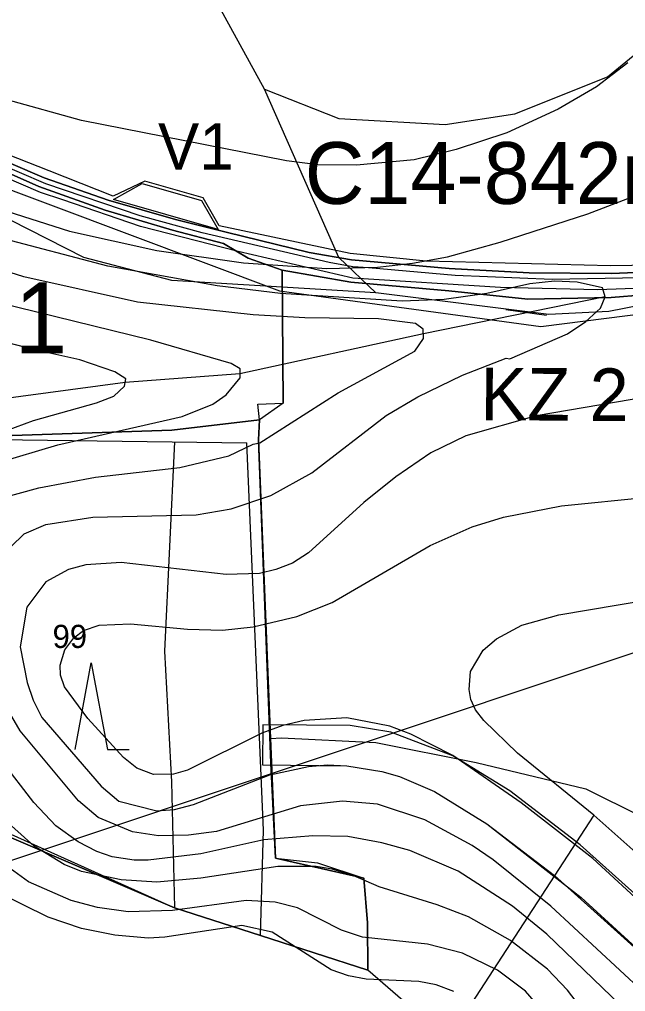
# Model space of a CAD drawing. Extents: x -662500 to -655523, y -1056000 to -1049993.
# Drawn here: x -660890.3 to -660694.1, y -1051979.7 to -1051664.9 of the extents above; entities that cross this region are included whole.
import ezdxf

# ---------------------------------------------------------------- set-up
doc = ezdxf.new("R2010")
doc.units = 0
for name, color, linetype in [('Vrstva 1', 7, 'Continuous'), ('Vrstva 12', 7, 'Continuous'), ('Vrstva 18', 7, 'Continuous'), ('Vrstva 22', 7, 'Continuous'), ('Vrstva 24', 7, 'Continuous'), ('Vrstva 47', 7, 'Continuous'), ('Vrstva 5', 7, 'Continuous'), ('Vrstva 54', 7, 'Continuous'), ('Vrstva 57', 7, 'Continuous'), ('Vrstva 6', 7, 'Continuous'), ('Vrstva 61', 7, 'Continuous'), ('Vrstva 7', 7, 'Continuous')]:
    doc.layers.add(name, color=color, linetype=linetype)

msp = doc.modelspace()

# ---------------------------------------------------------------- linework, layer by layer
at = {"layer": 'Vrstva 1'}
for p, q in [((-660921.87, -1051800.59), (-660816.75, -1051801.98)), ((-660909.2, -1051921.5), (-660840.14, -1051952.57))]:
    msp.add_line(p, q, dxfattribs=at)
msp.add_lwpolyline([(-660840.2, -1051801.67), (-660843.43, -1051869.43), (-660841.15, -1051911.77), (-660840.14, -1051952.57), (-660812.31, -1051961.52), (-660811.36, -1051927.44), (-660816.75, -1051801.98)], dxfattribs=at)
at = {"layer": 'Vrstva 12'}
msp.add_lwpolyline([(-660677.98, -1051748.43), (-660717.94, -1051749.1), (-660749.25, -1051747.86), (-660777.31, -1051745.37), (-660782.46, -1051745.02), (-660790.05, -1051743.6), (-660831.17, -1051734.05), (-660851.28, -1051728.5), (-660881.83, -1051718.2), (-660907.49, -1051707.19), (-660927.4, -1051698.64), (-660936.8, -1051698.75), (-660942.83, -1051699.66), (-660947.81, -1051703.59), (-660954.96, -1051712.4), (-660962.02, -1051729.41), (-660976.83, -1051765.96), (-661003.35, -1051828.87), (-661016.27, -1051860.08), (-661035.12, -1051906.08), (-661051.28, -1051948.02), (-661055.1, -1051959.21), (-661062.47, -1051984.12)], dxfattribs=at)
at = {"layer": 'Vrstva 22'}
msp.add_lwpolyline([(-660535.19, -1052035.73), (-660628.82, -1051995.51), (-660670.4, -1051966.64), (-660708.78, -1051932.15), (-660731.62, -1051914.69), (-660750.01, -1051903.34), (-660770.09, -1051895.71), (-660783.24, -1051893.57), (-660811.55, -1051893.32), (-660811.66, -1051906.32), (-660784.34, -1051906.56), (-660773.01, -1051908.4), (-660767.34, -1051910.1), (-660756, -1051914.92), (-660739, -1051925.41), (-660717.09, -1051942.16), (-660678.48, -1051976.85), (-660636.23, -1052006.19), (-660537.58, -1052047.09)], close=True, dxfattribs=at)
at = {"layer": 'Vrstva 24'}
for points in [[(-660811, -1051687.5), (-660839.5, -1051635.5), (-660864.5, -1051599.5), (-660895, -1051568), (-660922.5, -1051551.5), (-661100, -1051475), (-661134.5, -1051463.5), (-661164.5, -1051456.5), (-661191.5, -1051455), (-661224, -1051461.5), (-661242, -1051468.5), (-661258, -1051478)], [(-660775, -1051753.5), (-660841, -1051749.5), (-660869.5, -1051742), (-660893, -1051730), (-660959, -1051682), (-661010.5, -1051656), (-661075.5, -1051627), (-661105.5, -1051608.5), (-661240.5, -1051479), (-661251, -1051477), (-661258, -1051478)], [(-660811, -1051687.5), (-660787, -1051697), (-660752.5, -1051699), (-660730, -1051695.5), (-660700, -1051683.5), (-660678, -1051665.5)], [(-660775, -1051753.5), (-660787, -1051742), (-660811, -1051687.5)], [(-660511, -1051777), (-660532, -1051761), (-660562.5, -1051747), (-660577, -1051743), (-660585.5, -1051743), (-660623, -1051744.5), (-660699.5, -1051759.5), (-660719, -1051760.5), (-660775, -1051753.5)], [(-660947.48, -1051815.82), (-660921.87, -1051800.59), (-660841.03, -1051797.88), (-660812.66, -1051794.62), (-660812.99, -1051801.1), (-660809.04, -1051897.71)], [(-660812.31, -1051961.52), (-660840.14, -1051952.57), (-660909.06, -1051922.97), (-660928.7, -1051891.33), (-660972.42, -1051837.01), (-660947.48, -1051815.82)], [(-660809.04, -1051897.71), (-660805.5, -1051897.5), (-660775, -1051899), (-660742.5, -1051905.5), (-660707, -1051914), (-660671, -1051932), (-660495.5, -1052000)], [(-660809.04, -1051897.71), (-660807.45, -1051936.49), (-660778.91, -1051942.97), (-660777.67, -1051957.47), (-660777.56, -1051972.71)], [(-660777.56, -1051972.71), (-660812.31, -1051961.52)], [(-660328, -1052135), (-660352, -1052135.5), (-660451.5, -1052115.5), (-660661, -1052057), (-660695, -1052042.5), (-660723, -1052024.5), (-660747.5, -1052000), (-660756.5, -1051991), (-660777.56, -1051972.71)]]:
    msp.add_lwpolyline(points, dxfattribs=at)
at = {"layer": 'Vrstva 47'}
msp.add_line((-659729.76, -1051549.11), (-661071.93, -1051997.01), dxfattribs=at)
at = {"layer": 'Vrstva 5'}
for points in [[(-660677.92, -1051746.35), (-660698.73, -1051747.17), (-660725.37, -1051746.94), (-660751.25, -1051745.59), (-660782.88, -1051742.72), (-660796.61, -1051740.39), (-660823.47, -1051733.86), (-660839.84, -1051729.71), (-660861.64, -1051723.47), (-660882.34, -1051716.19), (-660904, -1051706.99), (-660926.53, -1051696.89), (-660937, -1051697), (-660944, -1051698.02), (-660951.11, -1051703.85), (-660956.58, -1051711.68), (-660963.94, -1051729.61), (-660977.17, -1051760.98), (-660988.12, -1051785.41), (-661015.38, -1051852.91), (-661036.37, -1051903.34), (-661051.42, -1051943.05), (-661057.07, -1051959.67), (-661064.71, -1051983.6)], [(-661064.71, -1051983.6), (-661057.07, -1051959.67), (-661051.42, -1051943.05), (-661036.37, -1051903.34), (-661015.38, -1051852.91), (-660988.12, -1051785.41), (-660977.17, -1051760.98), (-660963.94, -1051729.61), (-660956.58, -1051711.68), (-660951.11, -1051703.85), (-660944, -1051698.02), (-660937, -1051697), (-660926.53, -1051696.89), (-660904, -1051706.99), (-660882.34, -1051716.19), (-660861.64, -1051723.47), (-660839.84, -1051729.71), (-660823.47, -1051733.86), (-660796.61, -1051740.39), (-660782.88, -1051742.72), (-660751.25, -1051745.59), (-660725.37, -1051746.94), (-660698.73, -1051747.17), (-660677.92, -1051746.35)], [(-660905.01, -1051709.79), (-660884.03, -1051719.07), (-660862.56, -1051726.69), (-660840.82, -1051733.11), (-660824.31, -1051737.52), (-660816.34, -1051742.19), (-660805.3, -1051746.13), (-660805.01, -1051789.18), (-660812.66, -1051794.62), (-660841.03, -1051797.88), (-660921.87, -1051800.59)], [(-660677.41, -1051753.19), (-660698.84, -1051754.98), (-660725.74, -1051755.53), (-660751.3, -1051752.84), (-660783.08, -1051750.01), (-660805.3, -1051746.13), (-660816.34, -1051742.19), (-660824.31, -1051737.52), (-660840.82, -1051733.11), (-660862.56, -1051726.69), (-660884.03, -1051719.07), (-660905.01, -1051709.79)], [(-660909.06, -1051922.97), (-660840.14, -1051952.57), (-660812.31, -1051961.52), (-660777.56, -1051972.71), (-660777.67, -1051957.47), (-660778.91, -1051942.97), (-660807.46, -1051936.49), (-660808.94, -1051905.69), (-660812.99, -1051801.1), (-660812.66, -1051794.62), (-660813.15, -1051789.53), (-660805.01, -1051789.18), (-660805.3, -1051746.13), (-660783.08, -1051750.01), (-660751.3, -1051752.84), (-660725.74, -1051755.53), (-660698.84, -1051754.98), (-660677.41, -1051753.19)], [(-660872.35, -1051901.3), (-660867.1, -1051873.3), (-660861.85, -1051901.3), (-660854.85, -1051901.3)]]:
    msp.add_lwpolyline(points, dxfattribs=at)
msp.add_lwpolyline([(-660972.42, -1051837.01), (-660947.48, -1051815.82), (-660921.87, -1051800.59), (-660841.03, -1051797.88), (-660812.66, -1051794.62), (-660812.99, -1051801.1), (-660808.94, -1051905.69), (-660807.46, -1051936.49), (-660793.87, -1051937.97), (-660778.91, -1051942.97), (-660777.67, -1051957.47), (-660777.56, -1051972.71), (-660840.14, -1051952.57), (-660909.06, -1051922.97), (-660928.71, -1051891.33)], close=True, dxfattribs=at)
at = {"layer": 'Vrstva 54'}
msp.add_lwpolyline([(-661061.27, -1051999.59), (-661050.24, -1051980.46), (-661044.92, -1051955.41), (-661013, -1051874.07), (-660972.1, -1051779.61), (-660941.44, -1051708.81), (-660929, -1051706.7), (-660806.12, -1051752.81), (-660721.57, -1051764.39), (-660637.41, -1051753.69), (-660533.68, -1051733.93), (-660461.07, -1051720.1)], dxfattribs=at)
at = {"layer": 'Vrstva 57'}
msp.add_line((-660732.9, -1051758.83), (-660719.74, -1051760.71), dxfattribs=at)
for points in [[(-660700.73, -1051754.78), (-660759.57, -1051766.74), (-660818.96, -1051779.66), (-660856.09, -1051782.51), (-660932.64, -1051792.79), (-660951.67, -1051803.48), (-660977.9, -1051833.27), (-660993.8, -1051863.48), (-661010.03, -1051906.05), (-661027.36, -1051942.94), (-661034.91, -1051959.02), (-661044.14, -1051987.24), (-661052.39, -1052027.89)], [(-660704.42, -1051922.58), (-660744.1, -1051983.66), (-660851.38, -1052029.57)]]:
    msp.add_lwpolyline(points, dxfattribs=at)
at = {"layer": 'Vrstva 6'}
msp.add_lwpolyline([(-660670.4, -1051966.64), (-660708.78, -1051932.15), (-660731.62, -1051914.69), (-660750.01, -1051903.34), (-660770.09, -1051895.71), (-660783.24, -1051893.57), (-660811.55, -1051893.32), (-660811.66, -1051906.32), (-660784.34, -1051906.56), (-660773.01, -1051908.4), (-660767.34, -1051910.1), (-660756, -1051914.92), (-660739, -1051925.41), (-660717.09, -1051942.16), (-660678.48, -1051976.85)], dxfattribs=at)
at = {"layer": 'Vrstva 61'}
for points in [[(-660451.14, -1051707.63), (-660474.16, -1051711.28), (-660479.57, -1051712.14), (-660505.95, -1051715.78), (-660537.46, -1051721.89), (-660653.73, -1051742.33), (-660664.36, -1051744.2), (-660698.99, -1051744.72), (-660758.7, -1051743.25), (-660783.26, -1051740.76), (-660825.72, -1051731.73), (-660830.88, -1051722.68), (-660849.8, -1051717.29), (-660859.99, -1051722.17), (-660880.72, -1051714), (-660917.89, -1051699.35), (-660928.19, -1051693.51), (-660943.06, -1051695.75), (-660941.1, -1051708.76)], [(-660445.4, -1051716.9), (-660477.98, -1051719.69), (-660505.24, -1051723.42), (-660540.71, -1051729.9), (-660565.04, -1051734.35), (-660604.73, -1051741.6), (-660647.83, -1051749.47), (-660661.77, -1051751.01), (-660703.1, -1051752.45), (-660734.66, -1051751.75), (-660782.46, -1051748.72), (-660819.5, -1051740.1), (-660851.2, -1051731.93), (-660876.31, -1051723.38), (-660883.5, -1051720.93), (-660917.42, -1051706.42), (-660927.38, -1051702.16), (-660936.55, -1051702.02), (-660942.03, -1051702.79)]]:
    msp.add_lwpolyline(points, dxfattribs=at)
msp.add_lwpolyline([(-660859.87, -1051723.2), (-660850.58, -1051718.07), (-660831.36, -1051723.61), (-660825.99, -1051732.97)], close=True, dxfattribs=at)
at = {"layer": 'Vrstva 7'}
for p, q in [((-660693.36, -1051678.97), (-660703.57, -1051686.76)), ((-660703.57, -1051686.76), (-660715.9, -1051693.99)), ((-660870.22, -1051697.67), (-660894.32, -1051691.01)), ((-660715.9, -1051693.99), (-660732.62, -1051701.64)), ((-660803.9, -1051710.71), (-660870.22, -1051697.67)), ((-660732.62, -1051701.64), (-660748.92, -1051707.02)), ((-660748.92, -1051707.02), (-660762.52, -1051710.43)), ((-660793.7, -1051711.99), (-660803.9, -1051710.71)), ((-660762.52, -1051710.43), (-660781.23, -1051712.13)), ((-660781.23, -1051712.13), (-660793.7, -1051711.99)), ((-660706.4, -1051727.86), (-660683.73, -1051719.21)), ((-660896.87, -1051726.3), (-660874.19, -1051733.53)), ((-660734.74, -1051737.07), (-660706.4, -1051727.86)), ((-660861.72, -1051744.86), (-660897.15, -1051735.51)), ((-660874.19, -1051733.53), (-660845.85, -1051739.76)), ((-660751.75, -1051741.75), (-660734.74, -1051737.07)), ((-660845.85, -1051739.76), (-660817.79, -1051743.73)), ((-660763.09, -1051743.87), (-660751.75, -1051741.75)), ((-660888.93, -1051748.27), (-660904.52, -1051743.45)), ((-660826.29, -1051751.24), (-660861.72, -1051744.86)), ((-660817.79, -1051743.73), (-660790.86, -1051745.57)), ((-660790.86, -1051745.57), (-660774.43, -1051745.15)), ((-660774.43, -1051745.15), (-660763.09, -1051743.87)), ((-660852.09, -1051756.48), (-660888.93, -1051748.27)), ((-660805.89, -1051753.65), (-660826.29, -1051751.24)), ((-660725.11, -1051750.53), (-660739, -1051753.65)), ((-660717.17, -1051749.68), (-660725.11, -1051750.53)), ((-660709.8, -1051749.97), (-660717.17, -1051749.68)), ((-660701.58, -1051751.81), (-660709.8, -1051749.97)), ((-660700.73, -1051754.78), (-660701.58, -1051751.81)), ((-660847.83, -1051768.81), (-660904.8, -1051754.78)), ((-660766.49, -1051756.2), (-660805.89, -1051753.65)), ((-660739, -1051753.65), (-660752.88, -1051755.63)), ((-660702.29, -1051758.47), (-660700.73, -1051754.78)), ((-660814.67, -1051760.59), (-660852.09, -1051756.48)), ((-660752.88, -1051755.63), (-660766.49, -1051756.2)), ((-660797.95, -1051761.59), (-660814.67, -1051760.59)), ((-660706.97, -1051762.72), (-660702.29, -1051758.47)), ((-660885.39, -1051771.93), (-660922.38, -1051762.15)), ((-660774.14, -1051761.87), (-660797.95, -1051761.59)), ((-660762.09, -1051763.43), (-660774.14, -1051761.87)), ((-660759.69, -1051765.27), (-660762.09, -1051763.43)), ((-660712.92, -1051766.69), (-660706.97, -1051762.72)), ((-660759.54, -1051768.25), (-660759.69, -1051765.27)), ((-660731.63, -1051774.77), (-660712.92, -1051766.69)), ((-660821.76, -1051776.32), (-660847.83, -1051768.81)), ((-660762.38, -1051772.36), (-660759.54, -1051768.25)), ((-660870.79, -1051775.19), (-660885.39, -1051771.93)), ((-660787.18, -1051785.82), (-660762.38, -1051772.36)), ((-660859.45, -1051779.02), (-660870.79, -1051775.19)), ((-660818.92, -1051778.02), (-660821.76, -1051776.32)), ((-660746.93, -1051780.15), (-660732.76, -1051774.62)), ((-660732.76, -1051774.62), (-660731.63, -1051774.77)), ((-660855.91, -1051781.28), (-660859.45, -1051779.02)), ((-660818.92, -1051781), (-660818.92, -1051778.02)), ((-660761.39, -1051787.09), (-660746.93, -1051780.15)), ((-660856.34, -1051783.69), (-660855.91, -1051781.28)), ((-660823.46, -1051786.53), (-660818.92, -1051781)), ((-660859.74, -1051786.95), (-660856.34, -1051783.69)), ((-660827.71, -1051789.5), (-660823.46, -1051786.53)), ((-660812.55, -1051801.98), (-660787.18, -1051785.82)), ((-660672.11, -1051784.54), (-660723.12, -1051793.33)), ((-660885.81, -1051794.75), (-660865.41, -1051789.08)), ((-660865.41, -1051789.08), (-660859.74, -1051786.95)), ((-660837.63, -1051793.47), (-660827.71, -1051789.5)), ((-660771.59, -1051793.19), (-660761.39, -1051787.09)), ((-660905.37, -1051801.98), (-660885.81, -1051794.75)), ((-660877.88, -1051802.68), (-660837.63, -1051793.47)), ((-660795.68, -1051811.75), (-660771.59, -1051793.19)), ((-660723.12, -1051793.33), (-660745.8, -1051799.71)), ((-660814.67, -1051802.4), (-660812.55, -1051801.98)), ((-660745.8, -1051799.71), (-660757.14, -1051805.23)), ((-660901.69, -1051809.77), (-660877.88, -1051802.68)), ((-660822.61, -1051806.23), (-660814.67, -1051802.4)), ((-660757.14, -1051805.23), (-660768.47, -1051813.03)), ((-660838.48, -1051810.05), (-660822.61, -1051806.23)), ((-660865.69, -1051813.17), (-660838.48, -1051810.05)), ((-660809, -1051819.12), (-660795.68, -1051811.75)), ((-660884.11, -1051816.57), (-660865.69, -1051813.17)), ((-660768.47, -1051813.03), (-660778.82, -1051821.39)), ((-660903.67, -1051821.96), (-660884.11, -1051816.57)), ((-660714.9, -1051822.38), (-660647.73, -1051815.72)), ((-660821.76, -1051823.37), (-660809, -1051819.12)), ((-660833.1, -1051825.36), (-660821.76, -1051823.37)), ((-660778.82, -1051821.39), (-660796.82, -1051837.69)), ((-660733.61, -1051826.07), (-660714.9, -1051822.38)), ((-660881.85, -1051828.48), (-660866.54, -1051826.07)), ((-660866.54, -1051826.07), (-660833.1, -1051825.36)), ((-660743.81, -1051829.19), (-660733.61, -1051826.07)), ((-660888.79, -1051831.45), (-660881.85, -1051828.48)), ((-660757.42, -1051835.28), (-660743.81, -1051829.19)), ((-660897.44, -1051839.81), (-660888.79, -1051831.45)), ((-660789.16, -1051853.7), (-660757.42, -1051835.28)), ((-660796.82, -1051837.69), (-660801.92, -1051840.95)), ((-660874.48, -1051843.07), (-660881.85, -1051847.04)), ((-660868.81, -1051841.51), (-660874.48, -1051843.07)), ((-660857.47, -1051840.81), (-660868.81, -1051841.51)), ((-660823.46, -1051844.63), (-660857.47, -1051840.81)), ((-660807.3, -1051843.07), (-660812.69, -1051844.35)), ((-660801.92, -1051840.95), (-660807.3, -1051843.07)), ((-660812.69, -1051844.35), (-660823.46, -1051844.63)), ((-660881.85, -1051847.04), (-660887.94, -1051855.26)), ((-660715.75, -1051857.67), (-660667.85, -1051849.59)), ((-660887.94, -1051855.26), (-660890.07, -1051868.02)), ((-660800.5, -1051858.24), (-660789.16, -1051853.7)), ((-660814.67, -1051861.64), (-660800.5, -1051858.24)), ((-660727.66, -1051861.07), (-660715.75, -1051857.67)), ((-660869.66, -1051862.77), (-660864.56, -1051861.07)), ((-660864.56, -1051861.07), (-660854.35, -1051860.65)), ((-660854.35, -1051860.65), (-660835.93, -1051862.35)), ((-660824.59, -1051862.63), (-660814.67, -1051861.64)), ((-660735.88, -1051865.46), (-660727.66, -1051861.07)), ((-660875.61, -1051869.01), (-660872.78, -1051865.18)), ((-660872.78, -1051865.18), (-660869.66, -1051862.77)), ((-660835.93, -1051862.35), (-660824.59, -1051862.63)), ((-660890.07, -1051868.02), (-660887.8, -1051879.64)), ((-660740.27, -1051869.15), (-660735.88, -1051865.46)), ((-660877.17, -1051873.97), (-660875.61, -1051869.01)), ((-660744.38, -1051876.09), (-660740.27, -1051869.15)), ((-660877.03, -1051877.23), (-660877.17, -1051873.97)), ((-660875.75, -1051881.05), (-660877.03, -1051877.23)), ((-660744.81, -1051881.9), (-660744.38, -1051876.09)), ((-660887.8, -1051879.64), (-660885.96, -1051885.3)), ((-660868.24, -1051891.26), (-660875.75, -1051881.05)), ((-660744.24, -1051885.16), (-660744.81, -1051881.9)), ((-660890.07, -1051895.23), (-660895.03, -1051886.72)), ((-660885.96, -1051885.3), (-660883.12, -1051890.97)), ((-660742.68, -1051888.42), (-660744.24, -1051885.16)), ((-660739.99, -1051891.97), (-660742.68, -1051888.42)), ((-660883.12, -1051890.97), (-660863.85, -1051913.22)), ((-660856.62, -1051903.87), (-660868.24, -1051891.26)), ((-660805.04, -1051893.52), (-660811.84, -1051896.07)), ((-660798.23, -1051891.97), (-660805.04, -1051893.52)), ((-660784.34, -1051891.11), (-660798.23, -1051891.97)), ((-660770.46, -1051893.81), (-660784.34, -1051891.11)), ((-660729.08, -1051902.45), (-660739.99, -1051891.97)), ((-660871.22, -1051917.9), (-660890.07, -1051895.23)), ((-660811.84, -1051896.07), (-660835.93, -1051907.98)), ((-660763.65, -1051896.36), (-660770.46, -1051893.81)), ((-660750.05, -1051903.3), (-660763.65, -1051896.36)), ((-660704.42, -1051922.58), (-660729.08, -1051902.45)), ((-660885.67, -1051918.47), (-660896.16, -1051904.86)), ((-660852.37, -1051907.41), (-660856.62, -1051903.87)), ((-660727.94, -1051918.61), (-660750.05, -1051903.3)), ((-660846.98, -1051909.4), (-660852.37, -1051907.41)), ((-660840.46, -1051909.25), (-660846.98, -1051909.4)), ((-660835.93, -1051907.98), (-660840.46, -1051909.25)), ((-660809.29, -1051909.54), (-660796.82, -1051906.84)), ((-660796.82, -1051906.84), (-660790.58, -1051906.28)), ((-660790.58, -1051906.28), (-660784.34, -1051906.56)), ((-660784.34, -1051906.56), (-660773.01, -1051908.4)), ((-660773.01, -1051908.4), (-660767.34, -1051910.1)), ((-660833.95, -1051919.17), (-660809.29, -1051909.54)), ((-660767.34, -1051910.1), (-660756, -1051914.92)), ((-660863.85, -1051913.22), (-660858.18, -1051918.04)), ((-660756, -1051914.92), (-660739, -1051925.41)), ((-660878.59, -1051925.98), (-660885.67, -1051918.47)), ((-660864.84, -1051923.28), (-660871.22, -1051917.9)), ((-660858.18, -1051918.04), (-660845.85, -1051921.16)), ((-660785.76, -1051918.04), (-660799.37, -1051919.6)), ((-660774.43, -1051919.03), (-660785.76, -1051918.04)), ((-660704.7, -1051936.61), (-660727.94, -1051918.61)), ((-660845.85, -1051921.16), (-660840.18, -1051920.73)), ((-660840.18, -1051920.73), (-660833.95, -1051919.17)), ((-660799.37, -1051919.6), (-660826.58, -1051927.82)), ((-660759.12, -1051924.14), (-660774.43, -1051919.03)), ((-660853.79, -1051927.96), (-660864.84, -1051923.28)), ((-660743.81, -1051932.35), (-660759.12, -1051924.14)), ((-660682.59, -1051941.99), (-660704.42, -1051922.58)), ((-660885.53, -1051932.64), (-660892.9, -1051925.98)), ((-660871.36, -1051931.22), (-660878.59, -1051925.98)), ((-660845.28, -1051929.24), (-660853.79, -1051927.96)), ((-660826.58, -1051927.82), (-660835.65, -1051929.09)), ((-660739, -1051925.41), (-660708.53, -1051949.22)), ((-660865.27, -1051934.34), (-660871.36, -1051931.22)), ((-660835.65, -1051929.09), (-660845.28, -1051929.24)), ((-660811.27, -1051930.51), (-660831.68, -1051935.05)), ((-660795.4, -1051929.24), (-660811.27, -1051930.51)), ((-660784.06, -1051929.52), (-660795.4, -1051929.24)), ((-660773.01, -1051931.5), (-660784.06, -1051929.52)), ((-660875.89, -1051938.59), (-660885.53, -1051932.64)), ((-660860.31, -1051936.04), (-660865.27, -1051934.34)), ((-660763.94, -1051934.05), (-660773.01, -1051931.5)), ((-660748.35, -1051940.72), (-660763.94, -1051934.05)), ((-660737.01, -1051937.03), (-660743.81, -1051932.35)), ((-660853.22, -1051937.17), (-660860.31, -1051936.04)), ((-660848.68, -1051937.17), (-660853.22, -1051937.17)), ((-660831.68, -1051935.05), (-660848.68, -1051937.17)), ((-660718.31, -1051952.05), (-660737.01, -1051937.03)), ((-660673.66, -1051965.37), (-660704.7, -1051936.61)), ((-660887.37, -1051944.12), (-660895.73, -1051938.17)), ((-660870.22, -1051940.86), (-660875.89, -1051938.59)), ((-660806.74, -1051939.16), (-660831.68, -1051942.98)), ((-660794.27, -1051939.16), (-660806.74, -1051939.16)), ((-660789.16, -1051940.01), (-660794.27, -1051939.16)), ((-660782.36, -1051942.13), (-660789.16, -1051940.01)), ((-660730.78, -1051952.05), (-660748.35, -1051940.72)), ((-660857.47, -1051943.55), (-660870.22, -1051940.86)), ((-660845.85, -1051944.26), (-660857.47, -1051943.55)), ((-660831.68, -1051942.98), (-660845.85, -1051944.26)), ((-660773.86, -1051945.82), (-660782.36, -1051942.13)), ((-660881, -1051955.6), (-660898.57, -1051946.95)), ((-660873.63, -1051950.21), (-660887.37, -1051944.12)), ((-660755.15, -1051951.63), (-660773.86, -1051945.82)), ((-660865.12, -1051952.48), (-660873.63, -1051950.21)), ((-660816.94, -1051950.21), (-660840.75, -1051953.47)), ((-660807.59, -1051950.78), (-660816.94, -1051950.21)), ((-660708.53, -1051949.22), (-660678.48, -1051976.85)), ((-660855.2, -1051953.9), (-660865.12, -1051952.48)), ((-660800.36, -1051952.62), (-660807.59, -1051950.78)), ((-660786.05, -1051959.85), (-660800.36, -1051952.62)), ((-660744.95, -1051955.45), (-660755.15, -1051951.63)), ((-660719.58, -1051961.12), (-660730.78, -1051952.05)), ((-660688.54, -1051979.69), (-660718.31, -1051952.05)), ((-660870.22, -1051959.28), (-660881, -1051955.6)), ((-660840.75, -1051953.47), (-660855.2, -1051953.9)), ((-660731.34, -1051963.11), (-660744.95, -1051955.45)), ((-660859.45, -1051961.41), (-660870.22, -1051959.28)), ((-660818.36, -1051958.29), (-660843.3, -1051962.11)), ((-660808.58, -1051960.41), (-660818.36, -1051958.29)), ((-660848.68, -1051962.4), (-660859.45, -1051961.41)), ((-660843.3, -1051962.11), (-660848.68, -1051962.4)), ((-660789.45, -1051972.6), (-660808.58, -1051960.41)), ((-660779.24, -1051962.11), (-660786.05, -1051959.85)), ((-660758.27, -1051964.38), (-660779.24, -1051962.11)), ((-660695.63, -1051984.22), (-660719.58, -1051961.12)), ((-660746.93, -1051967.22), (-660758.27, -1051964.38)), ((-660719.44, -1051972.46), (-660731.34, -1051963.11)), ((-660735.59, -1051972.74), (-660746.93, -1051967.22)), ((-660783.78, -1051974.59), (-660789.45, -1051972.6)), ((-660778.11, -1051975.72), (-660783.78, -1051974.59)), ((-660726.53, -1051979.55), (-660735.59, -1051972.74)), ((-660712.89, -1051979.2), (-660719.44, -1051972.46)), ((-660761.1, -1051976.43), (-660778.11, -1051975.72)), ((-660755.44, -1051977.56), (-660761.1, -1051976.43)), ((-660749.77, -1051979.69), (-660755.44, -1051977.56)), ((-660715.61, -1051992.16), (-660726.53, -1051979.55)), ((-660708.67, -1051984.79), (-660712.89, -1051979.2))]:
    msp.add_line(p, q, dxfattribs=at)

# ---------------------------------------------------------------- texts
at = {"layer": 'Vrstva 18'}
msp.add_text('C14-842m', height=20, rotation=360, dxfattribs=at).set_placement((-660797.99, -1051724.66))
at = {"layer": 'Vrstva 24'}
msp.add_text('99', height=7.5, dxfattribs=at).set_placement((-660879.62, -1051868.44))
at = {"layer": 'Vrstva 54'}
msp.add_text('KZ 2', height=17, rotation=359.642, dxfattribs=at).set_placement((-660741.17, -1051794.67))
at = {"layer": 'Vrstva 57'}
msp.add_text('1', height=23, dxfattribs=at).set_placement((-660891.96, -1051773.08))
at = {"layer": 'Vrstva 61'}
msp.add_text('V1', height=15, dxfattribs=at).set_placement((-660845.51, -1051713.52))

doc.saveas('drawing.dxf')
